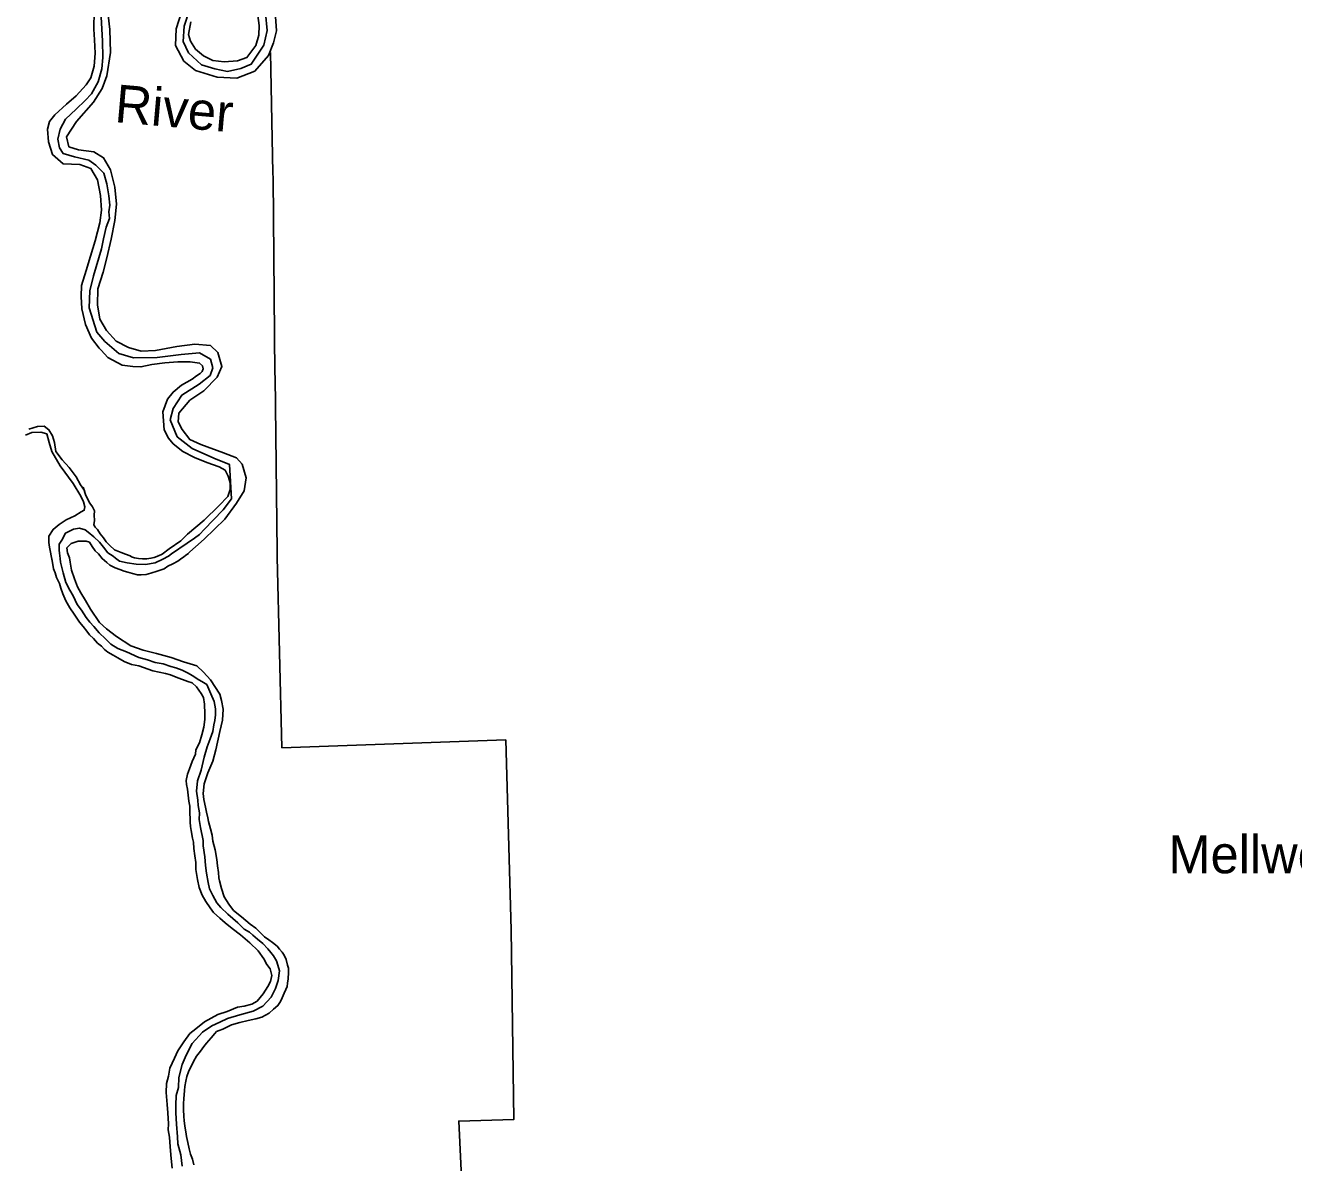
# Model space of a CAD drawing. Extents: x -939622 to -934222, y 1383701 to 1385301.
# Drawn here: x -935907.2 to -935854.1, y 1383869.6 to 1383917.3 of the extents above; entities that cross this region are included whole.
import ezdxf

# ---------------------------------------------------------------- set-up
doc = ezdxf.new("R2010")
doc.units = 0
for name, color, linetype in [('Level 2', 7, 'Continuous'), ('Level 24', 7, 'Continuous'), ('Level 7', 7, 'Continuous'), ('Level 9', 7, 'Continuous')]:
    doc.layers.add(name, color=color, linetype=linetype)

msp = doc.modelspace()

# ---------------------------------------------------------------- linework, layer by layer
at = {"layer": 'Level 2'}
for points in [[(-935897.172, 1383917.803), (-935897.107, 1383917.089), (-935897.243, 1383916.463), (-935897.775, 1383915.666), (-935898.202, 1383915.486), (-935898.766, 1383915.371), (-935899.296, 1383915.48), (-935899.853, 1383915.645), (-935900.397, 1383916.15), (-935900.62, 1383916.625), (-935900.584, 1383917.267), (-935900.354, 1383917.95)], [(-935904.063, 1383917.643), (-935904.009, 1383916.649), (-935903.986, 1383915.949), (-935904.03, 1383915.479), (-935904.183, 1383914.927), (-935904.46, 1383914.432), (-935904.725, 1383914.148), (-935905.102, 1383913.786), (-935905.549, 1383913.362), (-935905.775, 1383912.949), (-935905.871, 1383912.529), (-935905.807, 1383912.167), (-935905.657, 1383911.924), (-935905.182, 1383911.787), (-935904.57, 1383911.65)], [(-935904.57, 1383911.65), (-935904.279, 1383911.445), (-935903.943, 1383911.108), (-935903.82, 1383910.658), (-935903.743, 1383910.154), (-935903.696, 1383909.762), (-935903.731, 1383909.484), (-935903.708, 1383909.199), (-935903.845, 1383908.846), (-935903.966, 1383908.353), (-935904.045, 1383907.927), (-935904.27, 1383907.181), (-935904.374, 1383906.808), (-935904.539, 1383906.172), (-935904.555, 1383905.461), (-935904.239, 1383904.439), (-935903.902, 1383904.054), (-935903.324, 1383903.544), (-935902.699, 1383903.365), (-935901.716, 1383903.38), (-935900.709, 1383903.501), (-935899.937, 1383903.577), (-935899.474, 1383903.307), (-935899.377, 1383902.943), (-935899.5, 1383902.627), (-935899.958, 1383902.265), (-935900.677, 1383901.803), (-935901.045, 1383901.237), (-935901.17, 1383900.764), (-935900.881, 1383900.059), (-935900.25, 1383899.571), (-935899.342, 1383899.166), (-935898.678, 1383898.89), (-935898.596, 1383897.452), (-935898.947, 1383896.997), (-935899.366, 1383896.558), (-935899.734, 1383896.19), (-935899.947, 1383895.966)], [(-935903.559, 1383895.055), (-935903.778, 1383895.197), (-935903.958, 1383895.43), (-935904.129, 1383895.639), (-935904.363, 1383895.867), (-935904.599, 1383896.062), (-935904.728, 1383896.152), (-935904.964, 1383896.229), (-935905.214, 1383896.183), (-935905.549, 1383896.024), (-935905.712, 1383895.727), (-935905.824, 1383895.553), (-935905.82, 1383895.303), (-935905.801, 1383895.175), (-935905.78, 1383894.961)], [(-935899.947, 1383895.966), (-935900.155, 1383895.812), (-935900.452, 1383895.602), (-935901.119, 1383895.144)], [(-935903.559, 1383895.055), (-935903.457, 1383894.965), (-935903.286, 1383894.846), (-935902.972, 1383894.774), (-935902.593, 1383894.724), (-935902.205, 1383894.702), (-935901.802, 1383894.767), (-935901.473, 1383894.924), (-935901.243, 1383895.059), (-935901.119, 1383895.144)], [(-935904.367, 1383892.1), (-935904.54, 1383892.282), (-935904.681, 1383892.489), (-935904.884, 1383892.787), (-935905.062, 1383893.032), (-935905.225, 1383893.388), (-935905.373, 1383893.625), (-935905.538, 1383893.954), (-935905.648, 1383894.348), (-935905.712, 1383894.572), (-935905.766, 1383894.796), (-935905.78, 1383894.961)], [(-935900.664, 1383869.49), (-935900.717, 1383869.97), (-935900.85, 1383870.42), (-935900.867, 1383870.724), (-935900.903, 1383871.255), (-935900.928, 1383871.724), (-935900.934, 1383872.039), (-935900.916, 1383872.452), (-935900.823, 1383872.791), (-935900.811, 1383873.207), (-935900.661, 1383873.755), (-935900.501, 1383874.148), (-935900.245, 1383874.627), (-935899.808, 1383875.099), (-935899.429, 1383875.369), (-935899.082, 1383875.526), (-935898.765, 1383875.676), (-935898.245, 1383875.835), (-935897.691, 1383875.988), (-935897.283, 1383876.195), (-935896.936, 1383876.569), (-935896.754, 1383876.932), (-935896.641, 1383877.269), (-935896.586, 1383877.673), (-935896.653, 1383877.915), (-935896.721, 1383878.091), (-935896.844, 1383878.31), (-935896.953, 1383878.445), (-935897.08, 1383878.604), (-935897.284, 1383878.815), (-935897.509, 1383878.998), (-935897.702, 1383879.167), (-935897.844, 1383879.29), (-935898.073, 1383879.428), (-935898.341, 1383879.694), (-935898.75, 1383880.053), (-935899.046, 1383880.327), (-935899.22, 1383880.524), (-935899.375, 1383880.832), (-935899.524, 1383881.105), (-935899.577, 1383881.374), (-935899.648, 1383881.775), (-935899.69, 1383882.093), (-935899.721, 1383882.456), (-935899.782, 1383882.909), (-935899.791, 1383883.131), (-935899.9, 1383883.679), (-935899.951, 1383884.02), (-935899.935, 1383884.294), (-935900.001, 1383884.611), (-935900.01, 1383884.825), (-935900.071, 1383885.205), (-935900.027, 1383885.636), (-935899.871, 1383886.086), (-935899.74, 1383886.631), (-935899.614, 1383887.058), (-935899.5, 1383887.398), (-935899.386, 1383887.708), (-935899.34, 1383887.983), (-935899.297, 1383888.165), (-935899.267, 1383888.403), (-935899.269, 1383888.659), (-935899.322, 1383888.967), (-935899.472, 1383889.282), (-935899.63, 1383889.669), (-935899.767, 1383889.752), (-935900.042, 1383889.916), (-935900.219, 1383890.037), (-935900.445, 1383890.158), (-935900.661, 1383890.275), (-935900.934, 1383890.37), (-935901.134, 1383890.436), (-935901.455, 1383890.542), (-935901.798, 1383890.598), (-935902.117, 1383890.707), (-935902.482, 1383890.805), (-935903.002, 1383891.046), (-935903.357, 1383891.181), (-935903.647, 1383891.368), (-935903.881, 1383891.584), (-935904.138, 1383891.845), (-935904.367, 1383892.1)]]:
    msp.add_lwpolyline(points, dxfattribs=at)
at = {"layer": 'Level 7'}
for points in [[(-935896.963, 1383916.157), (-935896.867, 1383911.115), (-935896.852, 1383910.895)], [(-935896.852, 1383910.895), (-935896.785, 1383902.693), (-935896.766, 1383902.567), (-935896.686, 1383895.228)], [(-935896.686, 1383895.228), (-935896.692, 1383895.118), (-935896.683, 1383895.013), (-935896.486, 1383887.025), (-935887.112, 1383887.354), (-935886.89, 1383879.388), (-935886.772, 1383871.452), (-935889.082, 1383871.38), (-935888.724, 1383863.988), (-935888.377, 1383856.042), (-935888.055, 1383848.114), (-935891.908, 1383847.912), (-935891.53, 1383840.037), (-935891.265, 1383831.888), (-935891.146, 1383823.913)]]:
    msp.add_lwpolyline(points, dxfattribs=at)
at = {"layer": 'Level 9'}
for p, q in [((-935901.84, 1383894.995), (-935901.655, 1383895.07)), ((-935899.753, 1383884.853), (-935899.789, 1383885.104)), ((-935900.348, 1383884.25), (-935900.339, 1383884.491)), ((-935896.878, 1383878.866), (-935897.039, 1383878.975)), ((-935896.684, 1383878.711), (-935896.878, 1383878.866))]:
    msp.add_line(p, q, dxfattribs=at)
for points in [[(-935904.356, 1383917.924), (-935904.361, 1383917.133), (-935904.334, 1383916.688), (-935904.309, 1383916.13), (-935904.354, 1383915.581), (-935904.497, 1383915.102), (-935904.687, 1383914.808), (-935905.108, 1383914.339), (-935905.507, 1383913.994), (-935905.995, 1383913.545), (-935906.227, 1383913.274), (-935906.302, 1383912.947), (-935906.264, 1383912.422), (-935906.099, 1383911.885), (-935905.651, 1383911.5), (-935904.952, 1383911.471), (-935904.485, 1383911.304), (-935904.211, 1383910.827), (-935904.088, 1383910.169), (-935904.044, 1383909.557), (-935904.111, 1383909.025), (-935904.306, 1383908.271), (-935904.51, 1383907.625), (-935904.682, 1383907.025), (-935904.884, 1383906.403), (-935904.898, 1383905.942), (-935904.875, 1383905.423), (-935904.713, 1383904.768), (-935904.466, 1383904.192), (-935904.14, 1383903.774), (-935904.054, 1383903.68), (-935903.781, 1383903.375), (-935903.176, 1383903.051), (-935902.737, 1383903.003), (-935902.394, 1383902.986), (-935901.935, 1383903.083), (-935901.386, 1383903.149), (-935900.844, 1383903.203), (-935900.332, 1383903.202), (-935899.937, 1383903.147), (-935899.817, 1383903.027), (-935899.781, 1383902.905), (-935899.832, 1383902.792), (-935899.916, 1383902.708), (-935900.06, 1383902.605), (-935900.248, 1383902.471)], [(-935900.69, 1383917.847), (-935900.913, 1383917.15), (-935900.939, 1383916.454), (-935900.594, 1383915.802), (-935900.113, 1383915.406), (-935899.2, 1383915.125), (-935898.377, 1383915.087), (-935897.626, 1383915.379), (-935897.051, 1383916.032), (-935896.838, 1383916.564), (-935896.719, 1383917.064), (-935896.76, 1383917.67)], [(-935900.47, 1383895.12), (-935899.749, 1383895.766), (-935898.876, 1383896.608), (-935898.388, 1383897.277), (-935898.069, 1383897.791), (-935897.991, 1383898.334), (-935898.157, 1383898.907), (-935898.395, 1383899.171), (-935898.94, 1383899.379), (-935899.891, 1383899.729), (-935900.35, 1383899.941), (-935900.664, 1383900.36), (-935900.835, 1383900.686), (-935900.809, 1383901.045), (-935900.35, 1383901.59), (-935899.752, 1383901.976), (-935899.195, 1383902.554), (-935899.001, 1383903.004), (-935899.167, 1383903.586), (-935899.484, 1383903.884), (-935900.139, 1383903.932), (-935900.886, 1383903.839), (-935901.784, 1383903.679), (-935902.383, 1383903.651), (-935902.912, 1383903.802), (-935903.425, 1383904.061), (-935903.839, 1383904.504), (-935904.111, 1383904.992), (-935904.208, 1383905.591), (-935904.2, 1383906.259), (-935903.973, 1383906.948), (-935903.827, 1383907.551), (-935903.633, 1383908.341), (-935903.49, 1383909.115), (-935903.419, 1383909.811), (-935903.489, 1383910.522), (-935903.671, 1383911.242), (-935903.961, 1383911.751), (-935904.361, 1383912.002), (-935905.01, 1383912.086), (-935905.407, 1383912.211), (-935905.517, 1383912.62), (-935905.094, 1383913.263), (-935904.379, 1383914.08), (-935904.023, 1383914.655), (-935903.827, 1383915.178), (-935903.662, 1383916.159), (-935903.689, 1383917.13), (-935903.762, 1383917.724)], [(-935897.504, 1383917.809), (-935897.439, 1383917.297), (-935897.461, 1383916.89), (-935897.587, 1383916.456), (-935897.957, 1383915.947), (-935898.355, 1383915.813), (-935898.902, 1383915.768), (-935899.378, 1383915.83), (-935899.779, 1383916.02), (-935900.114, 1383916.306), (-935900.318, 1383916.64), (-935900.4, 1383916.917), (-935900.307, 1383917.449)], [(-935900.248, 1383902.471), (-935900.688, 1383902.224), (-935901.046, 1383901.931), (-935901.287, 1383901.636), (-935901.479, 1383901.098), (-935901.425, 1383900.348), (-935901.245, 1383900.001), (-935901.046, 1383899.763), (-935900.645, 1383899.44), (-935900.143, 1383899.183), (-935899.628, 1383898.978), (-935899.113, 1383898.791), (-935898.869, 1383898.659), (-935898.745, 1383898.401), (-935898.654, 1383898.133), (-935898.655, 1383897.844), (-935898.749, 1383897.553), (-935899.137, 1383897.163), (-935899.744, 1383896.566), (-935900.445, 1383895.975), (-935900.722, 1383895.697), (-935901.204, 1383895.359), (-935901.498, 1383895.137), (-935901.655, 1383895.07)], [(-935904.709, 1383897.638), (-935904.761, 1383897.805), (-935904.93, 1383898.047), (-935905.107, 1383898.379), (-935905.396, 1383898.762), (-935905.69, 1383899.09), (-935905.955, 1383899.444), (-935906.016, 1383899.815), (-935906.099, 1383900.102), (-935906.247, 1383900.353), (-935906.452, 1383900.498), (-935906.73, 1383900.493), (-935907.085, 1383900.372)], [(-935907.234, 1383900.126), (-935906.963, 1383900.24), (-935906.583, 1383900.254), (-935906.338, 1383900.179), (-935906.241, 1383899.818), (-935906.125, 1383899.433), (-935905.779, 1383898.844), (-935905.237, 1383898.101), (-935904.908, 1383897.569), (-935904.799, 1383897.326), (-935904.749, 1383897.122), (-935904.766, 1383896.978), (-935904.893, 1383896.905), (-935905.164, 1383896.75), (-935905.525, 1383896.581), (-935905.816, 1383896.374), (-935906.063, 1383896.172), (-935906.244, 1383895.896), (-935906.255, 1383895.631), (-935906.222, 1383895.434), (-935906.107, 1383894.853)], [(-935902.842, 1383895.063), (-935903.045, 1383895.142), (-935903.221, 1383895.207), (-935903.494, 1383895.316), (-935903.697, 1383895.5), (-935903.854, 1383895.655), (-935903.966, 1383895.824), (-935904.1, 1383895.994), (-935904.216, 1383896.169), (-935904.317, 1383896.274), (-935904.371, 1383896.363), (-935904.343, 1383896.547), (-935904.346, 1383896.773), (-935904.342, 1383896.947), (-935904.422, 1383897.125), (-935904.528, 1383897.273), (-935904.616, 1383897.427), (-935904.709, 1383897.638), (-935904.819, 1383897.945)], [(-935905.384, 1383894.99), (-935905.469, 1383895.193), (-935905.493, 1383895.4), (-935905.318, 1383895.588), (-935905.021, 1383895.686), (-935904.688, 1383895.681), (-935904.552, 1383895.639), (-935904.442, 1383895.456), (-935904.305, 1383895.282), (-935904.166, 1383895.145), (-935904.018, 1383894.959)], [(-935900.4, 1383895.17), (-935900.47, 1383895.12), (-935900.52, 1383895.083), (-935900.6, 1383895.02), (-935900.741, 1383894.926), (-935900.85, 1383894.842), (-935901.051, 1383894.728), (-935901.273, 1383894.635), (-935901.417, 1383894.522), (-935901.717, 1383894.418), (-935901.982, 1383894.341), (-935902.178, 1383894.291), (-935902.379, 1383894.264), (-935902.541, 1383894.275), (-935902.743, 1383894.326), (-935902.943, 1383894.387), (-935903.097, 1383894.428), (-935903.273, 1383894.498), (-935903.479, 1383894.564), (-935903.695, 1383894.67), (-935903.819, 1383894.787), (-935903.914, 1383894.874), (-935904.018, 1383894.959), (-935904.089, 1383895.029)], [(-935902.842, 1383895.063), (-935902.784, 1383895.023), (-935902.666, 1383894.978), (-935902.5, 1383894.958), (-935902.329, 1383894.939), (-935902.146, 1383894.944), (-935901.972, 1383894.967), (-935901.841, 1383894.995), (-935901.84, 1383894.995)], [(-935901.686, 1383895.103), (-935901.685, 1383895.104)], [(-935900.339, 1383884.491), (-935900.348, 1383884.572), (-935900.384, 1383884.787), (-935900.421, 1383885.042), (-935900.443, 1383885.282), (-935900.485, 1383885.491), (-935900.504, 1383885.656), (-935900.448, 1383885.913), (-935900.359, 1383886.147), (-935900.247, 1383886.445), (-935900.103, 1383886.762), (-935900.09, 1383886.931), (-935899.946, 1383887.233), (-935899.847, 1383887.56), (-935899.76, 1383887.891), (-935899.712, 1383888.214), (-935899.71, 1383888.448), (-935899.724, 1383888.848), (-935899.774, 1383889.135), (-935899.866, 1383889.295), (-935900.062, 1383889.576), (-935900.253, 1383889.742), (-935900.432, 1383889.794), (-935900.917, 1383889.982), (-935901.154, 1383890.075), (-935901.371, 1383890.132), (-935901.897, 1383890.25), (-935902.488, 1383890.459), (-935902.789, 1383890.508), (-935903.099, 1383890.644), (-935903.355, 1383890.79), (-935903.562, 1383890.898), (-935903.782, 1383891.034), (-935903.917, 1383891.138), (-935904.044, 1383891.285), (-935904.209, 1383891.404), (-935904.386, 1383891.604), (-935904.543, 1383891.75), (-935904.662, 1383891.915), (-935904.808, 1383892.1), (-935904.966, 1383892.282), (-935905.192, 1383892.622), (-935905.373, 1383892.885), (-935905.543, 1383893.175), (-935905.663, 1383893.472), (-935905.75, 1383893.71), (-935905.81, 1383893.904), (-935905.928, 1383894.154), (-935905.981, 1383894.348), (-935906.056, 1383894.529), (-935906.09, 1383894.697), (-935906.107, 1383894.853), (-935906.122, 1383894.96)], [(-935905.384, 1383894.99), (-935905.355, 1383894.798), (-935905.298, 1383894.469), (-935905.182, 1383894.102), (-935905.05, 1383893.772), (-935904.917, 1383893.517), (-935904.719, 1383893.195), (-935904.499, 1383892.831), (-935904.123, 1383892.273), (-935903.839, 1383892.007), (-935903.41, 1383891.685), (-935902.811, 1383891.298), (-935902.299, 1383891.111), (-935901.737, 1383890.979), (-935901.129, 1383890.8), (-935900.617, 1383890.631), (-935900.057, 1383890.451), (-935899.774, 1383890.194), (-935899.477, 1383889.869), (-935899.082, 1383889.263), (-935899.023, 1383889.009), (-935898.953, 1383888.638), (-935898.976, 1383888.18), (-935899.092, 1383887.704), (-935899.259, 1383886.942), (-935899.375, 1383886.466), (-935899.595, 1383885.967), (-935899.741, 1383885.509), (-935899.789, 1383885.104)], [(-935899.753, 1383884.853), (-935899.684, 1383884.539), (-935899.642, 1383884.329), (-935899.593, 1383884.09), (-935899.559, 1383883.929), (-935899.478, 1383883.627), (-935899.414, 1383883.364), (-935899.382, 1383883.103), (-935899.282, 1383882.748), (-935899.217, 1383882.347), (-935899.182, 1383882.077), (-935899.15, 1383881.795), (-935899.129, 1383881.579), (-935899.096, 1383881.445), (-935899.021, 1383881.122), (-935898.906, 1383880.782), (-935898.711, 1383880.463), (-935898.521, 1383880.206), (-935898.18, 1383879.942), (-935897.824, 1383879.636), (-935897.576, 1383879.46), (-935897.217, 1383879.103), (-935897.039, 1383878.975)], [(-935897.48, 1383878.515), (-935897.837, 1383878.845), (-935898.228, 1383879.18), (-935898.574, 1383879.447), (-935898.872, 1383879.682), (-935899.094, 1383879.878), (-935899.352, 1383880.123), (-935899.499, 1383880.321), (-935899.68, 1383880.583), (-935899.829, 1383880.844), (-935899.949, 1383881.163), (-935900.024, 1383881.506), (-935900.093, 1383881.923), (-935900.093, 1383882.22), (-935900.136, 1383882.49), (-935900.172, 1383882.805), (-935900.197, 1383883.069), (-935900.235, 1383883.239), (-935900.292, 1383883.556), (-935900.315, 1383883.727), (-935900.335, 1383883.904), (-935900.337, 1383884.072), (-935900.348, 1383884.25)], [(-935896.684, 1383878.711), (-935896.585, 1383878.585), (-935896.476, 1383878.461), (-935896.398, 1383878.328), (-935896.305, 1383878.144), (-935896.251, 1383877.914), (-935896.214, 1383877.786), (-935896.212, 1383877.608), (-935896.232, 1383877.343), (-935896.26, 1383877.159), (-935896.271, 1383877.023), (-935896.318, 1383876.896), (-935896.392, 1383876.734), (-935896.479, 1383876.542), (-935896.553, 1383876.387), (-935896.659, 1383876.218), (-935896.847, 1383876.063), (-935897.023, 1383875.907), (-935897.33, 1383875.737), (-935897.583, 1383875.663), (-935897.902, 1383875.594), (-935898.247, 1383875.507), (-935898.602, 1383875.416), (-935898.96, 1383875.234), (-935899.111, 1383875.173), (-935899.224, 1383875.134), (-935899.3, 1383875.053), (-935899.457, 1383874.865), (-935899.64, 1383874.65), (-935899.761, 1383874.502), (-935899.897, 1383874.306), (-935900.059, 1383874.097), (-935900.197, 1383873.879), (-935900.395, 1383873.444), (-935900.473, 1383873.246), (-935900.519, 1383873.052), (-935900.56, 1383872.829), (-935900.571, 1383872.666), (-935900.603, 1383872.31), (-935900.609, 1383872.111), (-935900.605, 1383871.868), (-935900.591, 1383871.576), (-935900.577, 1383871.408), (-935900.549, 1383871.159), (-935900.51, 1383870.932), (-935900.486, 1383870.734), (-935900.431, 1383870.486), (-935900.37, 1383870.214)], [(-935901.082, 1383869.412), (-935901.13, 1383869.817), (-935901.167, 1383870.303), (-935901.191, 1383870.703), (-935901.247, 1383871.017), (-935901.24, 1383871.267), (-935901.267, 1383871.72), (-935901.289, 1383872.077), (-935901.331, 1383872.582), (-935901.326, 1383872.952), (-935901.236, 1383873.264), (-935901.176, 1383873.597), (-935900.99, 1383874.02), (-935900.842, 1383874.316), (-935900.592, 1383874.705), (-935900.341, 1383875.043), (-935900.088, 1383875.245), (-935899.73, 1383875.532), (-935899.172, 1383875.851), (-935898.777, 1383875.97), (-935898.347, 1383876.151), (-935898.069, 1383876.188), (-935897.753, 1383876.275), (-935897.529, 1383876.402), (-935897.279, 1383876.716), (-935897.078, 1383877.016), (-935896.964, 1383877.227), (-935896.905, 1383877.484), (-935896.982, 1383877.755), (-935897.119, 1383877.935), (-935897.24, 1383878.184), (-935897.48, 1383878.515)], [(-935900.37, 1383870.214), (-935900.319, 1383869.993), (-935900.229, 1383869.782), (-935900.18, 1383869.539)]]:
    msp.add_lwpolyline(points, dxfattribs=at)

# ---------------------------------------------------------------- texts
at = {"layer": 'Level 24'}
msp.add_text('Mellwood', height=1.584, dxfattribs=at).set_placement((-935859.357, 1383881.764))
at = {"layer": 'Level 9'}
msp.add_text('River', height=1.584, rotation=355, dxfattribs=at).set_placement((-935903.525, 1383913.247))

doc.saveas('drawing.dxf')
